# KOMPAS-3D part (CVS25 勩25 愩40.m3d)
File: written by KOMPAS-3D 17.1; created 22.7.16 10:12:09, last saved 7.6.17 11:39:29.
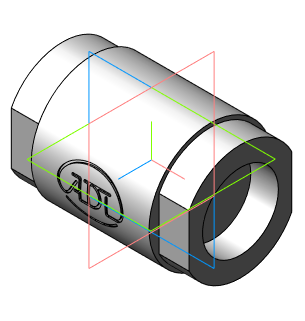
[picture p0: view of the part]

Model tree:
1. Операция без истории:2  (labels: Сталь 20  ГОСТ 1050-88)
